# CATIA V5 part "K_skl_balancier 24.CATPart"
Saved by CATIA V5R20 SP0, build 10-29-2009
Part number: skl_balancier 24
Publications: "longueur axe pivot", "liaison 24/25", "liaison 24/33 sur 24", "liaison 24/28", "Plan.00", "Droite.1", "Droite.2", "Droite.3", "Droite.4", "Droite.5"
Bounding box of the stored display mesh (mm): x 0 to 150, y 340 to 1060, z 0 to 0
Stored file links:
  G:\Khaled_CFAO_2011\SIL\SIL_GR2\mdardier\Khaled\CAD_ThinkMOTION\K_skl_balancier 24.CATPart
  G:\Khaled_CFAO_2011\SIL\SIL_GR2\mdardier\Khaled\CAD_ThinkMOTION\K_skl_ass_tandem.CATProduct
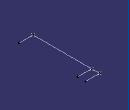
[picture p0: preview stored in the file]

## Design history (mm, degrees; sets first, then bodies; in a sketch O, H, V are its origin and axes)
External parameters (linked from other documents)
  `External.longueur axe pivot` = 150 mm
Set1
  Point1 "liaison 24/25": linked copy from another document
  Point2 "liaison 24/33 sur 24": linked copy from another document
  Point3 "liaison 24/28": linked copy from another document
  Plane1 "Plan.00": linked copy from another document
Set2
  Line1: type PtPt, FirstPoint Point1, SecondPoint Point2
  Line2: type PtPt, FirstPoint Point2, SecondPoint Point3
  Line3: type Normal, RefPoint Point1, RefSkin Plane1, Start 0, End 150 {= `External.longueur axe pivot`}
  Line4: type Normal, RefPoint Point2, RefSkin Plane1, Start 0, End 150 {= `External.longueur axe pivot`}
  Line5: type Normal, RefPoint Point3, RefSkin Plane1, Start 0, End 150 {= `External.longueur axe pivot`}
Body1 (main body)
